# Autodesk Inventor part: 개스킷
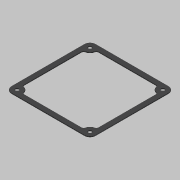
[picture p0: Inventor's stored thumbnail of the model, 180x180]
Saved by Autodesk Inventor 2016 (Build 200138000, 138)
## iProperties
Created: 2019-04
Part Number: 개스킷
Material: 고무
Document SubType Name: Modeling
Designer: mduedu
Density: 0.93 g/cm^3
Appearance: 고무 - 검은색 - 버전 1.1
Mass: 2.32152 g
Surface Area: 58.0824 cm^2
Volume: 2.49626 cm^3
Author: mduedu
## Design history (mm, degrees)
sketch "스케치1"
  geometry: L1 (52.5, 52.5)-(-52.5, 52.5); L2 (-52.5, 52.5)-(-52.5, -52.5); L3 (-52.5, -52.5)-(52.5, -52.5); L4 (52.5, -52.5)-(52.5, 52.5); L5 (52.5, 52.5)-(-52.5, -52.5); L6 (-52.5, 52.5)-(52.5, -52.5); 1 further point
  constraints: 12 end point, 2 midpoint, 2 parallel, 1 horizontal, 1 perpendicular
  dimensions: "d0" = 105 distance of L3.end L2.end; "d1" = 105 distance of L2.end L1.end
extrude "돌출1" new body sketch "스케치1" distance "d2" = 1; taper "d3" = 0 deg
sketch "스케치2"
  geometry: L1 (-52.5, -52.5)-(52.5, -52.5) reference; L2 (52.5, -52.5)-(52.5, 52.5) reference; L3 (52.5, 52.5)-(-52.5, 52.5) reference; L4 (-52.5, 52.5)-(-52.5, -52.5) reference; L5 (-46.5, 46.5)-(46.5, 46.5); L6 (46.5, 46.5)-(46.5, -46.5); L7 (46.5, -46.5)-(-46.5, -46.5); L8 (-46.5, -46.5)-(-46.5, 46.5); 1 further point
  constraints: 8 end point, 3 other
  dimensions: "d4" = 6 distance between parallel lines of L5 L3
extrude "돌출2" cut sketch "스케치2" stored distance "d5" = 1; taper "d6" = 0 deg
fillet "모깎기1" dims "d7" = 7
sketch "스케치3"
  geometry: A1 r 7 centre (-45.5, 45.5) between (-45.5, 52.5) and (-52.5, 45.5) reference; A2 r 7 centre (-45.5, -45.5) between (-52.5, -45.5) and (-45.5, -52.5) reference; A3 r 7 centre (45.5, -45.5) between (45.5, -52.5) and (52.5, -45.5) reference; A4 r 7 centre (45.5, 45.5) between (52.5, 45.5) and (45.5, 52.5) reference; 5 further points
  constraints: 4 coincident, 4 vertical alignment, 8 other
extrude "돌출3" join sketch "스케치3" stored distance "d8" = 1; taper "d9" = 0 deg
fillet "모깎기2" dims "d10" = 3
sketch "스케치4"
  geometry: A1 r 7 centre (-45.5, 45.5) between (-45.5, 52.5) and (-52.5, 45.5) reference; A2 r 7 centre (45.5, 45.5) between (52.5, 45.5) and (45.5, 52.5) reference; A3 r 7 centre (45.5, -45.5) between (45.5, -52.5) and (52.5, -45.5) reference; A4 r 7 centre (-45.5, -45.5) between (-52.5, -45.5) and (-45.5, -52.5) reference; 5 further points
  constraints: 4 coincident
hole "구멍1" sketch "스케치4" at (-45.5, 45.5), (45.5, 45.5), (45.5, -45.5), (-45.5, -45.5) diameter "d11" = 4.5; stored, may be unused: countersink angle "d15" = 90 deg, drill point angle "d17" = 118 deg; dims "d12" = 6, "d13" = 4, "d14" = 2, "d16" = 8
node "솔리드1"
node "투영된 루프1"
